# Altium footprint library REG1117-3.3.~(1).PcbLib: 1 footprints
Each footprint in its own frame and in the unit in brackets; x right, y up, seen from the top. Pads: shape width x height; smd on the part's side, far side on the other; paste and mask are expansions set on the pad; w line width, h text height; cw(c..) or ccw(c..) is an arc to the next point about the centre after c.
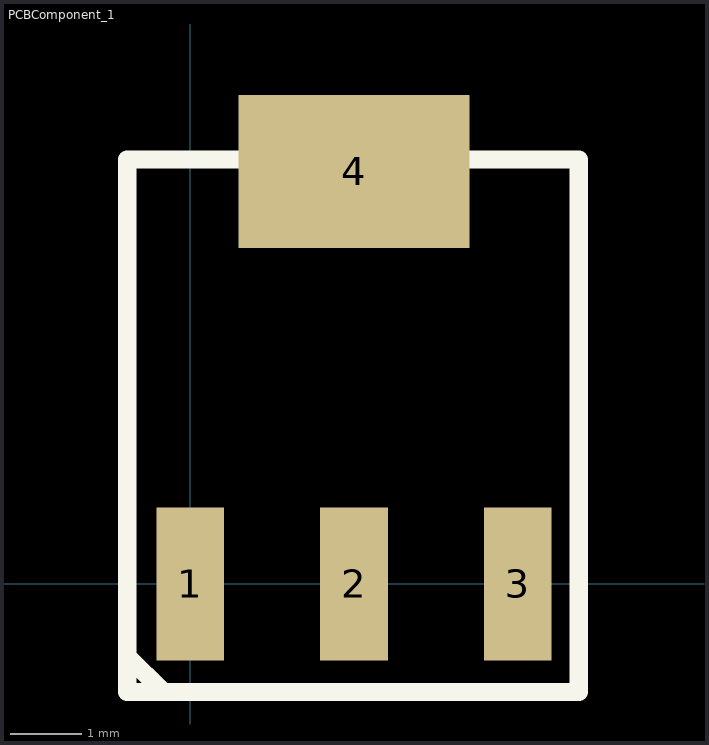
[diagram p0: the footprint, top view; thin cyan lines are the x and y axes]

## PCBComponent_1 [mm]
pads (4):
  rect 0.95x2.15 all layers, no hole: 1(0,0) 2(2.3,0) 3(4.6,0)
  rect 3.25x2.15 all layers, no hole: 4(2.3,5.8)
Top Overlay:
  lines w0.254: -0.889,-1.016 -0.381,-1.524 ; -0.889,-1.524 -0.889,5.969 5.461,5.969 5.461,-1.524 -0.889,-1.524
